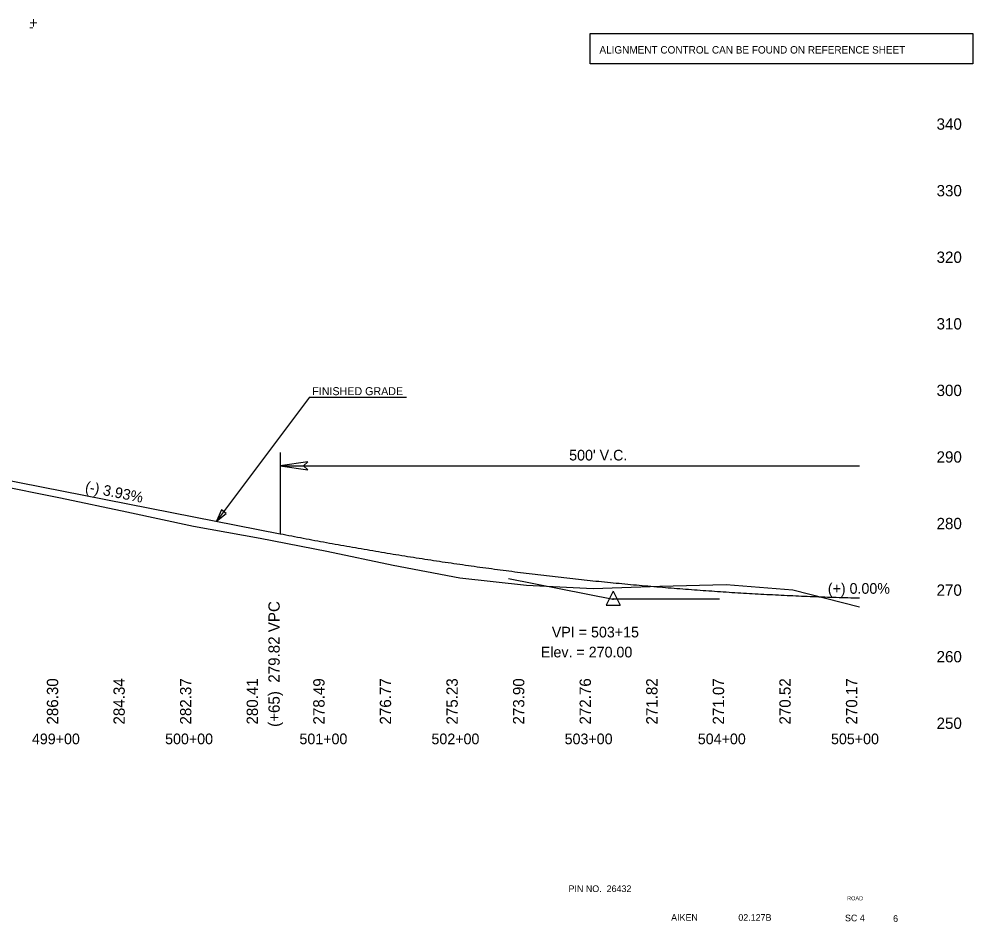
# Model space of a CAD drawing. Extents: x 48556 to 51363, y 45290 to 53458.
# Drawn here: x 50057 to 50773, y 46530 to 47208 of the extents above; entities that cross this region are included whole.
import ezdxf

# ---------------------------------------------------------------- set-up
doc = ezdxf.new("R2010")
doc.units = 0
for name, color, linetype in [('Level 1', 7, 'Continuous'), ('Level 24', 7, 'Continuous'), ('Level 25', 7, 'Continuous'), ('Level 40', 7, 'Continuous'), ('Level 41', 7, 'Continuous'), ('Level 42', 7, 'Continuous'), ('Level 43', 7, 'Continuous'), ('Level 45', 7, 'Continuous')]:
    doc.layers.add(name, color=color, linetype=linetype)

msp = doc.modelspace()

# ---------------------------------------------------------------- linework, layer by layer
at = {"layer": 'Level 1'}
for p, q in [((50275, 46924.38), (50205.18, 46831.33)), ((50275, 46924.38), (50347.79, 46924.38)), ((50502.91, 46778.85), (50497.66, 46768.35)), ((50502.91, 46778.85), (50508.16, 46768.35)), ((50497.66, 46768.35), (50508.16, 46768.35))]:
    msp.add_line(p, q, dxfattribs=at)
msp.add_lwpolyline([(50252.91, 46872.85), (50273.68, 46869.85), (50270.48, 46872.85), (50273.68, 46875.85)], close=True, dxfattribs=at)
msp.add_circle((50502.91, 46772.85), 0.375, dxfattribs=at)
at = {"layer": 'Level 24'}
for p, q in [((50208.79, 46839.88), (50205.18, 46831.33)), ((50212.39, 46837.17), (50208.79, 46839.88)), ((50205.18, 46831.33), (50212.39, 46837.17))]:
    msp.add_line(p, q, dxfattribs=at)
at = {"layer": 'Level 25'}
msp.add_lwpolyline([(50485.79, 47197.68), (50773.11, 47197.68), (50773.11, 47174.97), (50485.79, 47174.97)], close=True, dxfattribs=at)
at = {"layer": 'Level 40'}
msp.add_lwpolyline([(50037.91, 46858.99), (50087.91, 46848.83), (50137.91, 46838.48), (50187.91, 46827.57), (50237.91, 46818.6), (50287.91, 46808.73), (50337.91, 46798.21), (50387.91, 46788.76), (50437.91, 46783.23), (50487.91, 46780.68), (50537.91, 46782.44), (50587.91, 46783.93), (50637.91, 46779.7), (50687.91, 46767.11)], dxfattribs=at)
at = {"layer": 'Level 41'}
for p, q in [((50252.91, 46882.85), (50252.91, 46821.95)), ((50252.91, 46872.85), (50687.91, 46872.85)), ((50424.41, 46788.27), (50502.91, 46772.85)), ((50582.91, 46772.85), (50502.91, 46772.85))]:
    msp.add_line(p, q, dxfattribs=at)
at = {"layer": 'Level 45'}
msp.add_line((50037.91, 46864.18), (50252.91, 46821.95), dxfattribs=at)
msp.add_spline([(50252.91, 46821.95), (50261.61, 46820.26), (50270.31, 46818.59), (50279.01, 46816.96), (50287.71, 46815.36), (50296.41, 46813.78), (50305.11, 46812.24), (50313.81, 46810.72), (50322.51, 46809.23), (50331.21, 46807.78), (50339.91, 46806.35), (50348.61, 46804.96), (50357.31, 46803.59), (50366.01, 46802.25), (50374.71, 46800.94), (50383.41, 46799.67), (50392.11, 46798.42), (50400.81, 46797.2), (50409.51, 46796.01), (50418.21, 46794.85), (50426.91, 46793.72), (50435.61, 46792.63), (50444.31, 46791.56), (50453.01, 46790.52), (50461.71, 46789.51), (50470.41, 46788.53), (50479.11, 46787.58), (50487.81, 46786.65), (50496.51, 46785.76), (50505.21, 46784.9), (50513.91, 46784.07), (50522.61, 46783.27), (50531.31, 46782.5), (50540.01, 46781.75), (50548.71, 46781.04), (50557.41, 46780.36), (50566.11, 46779.7), (50574.81, 46779.08), (50583.51, 46778.49), (50592.21, 46777.92), (50600.91, 46777.39), (50609.61, 46776.88), (50618.31, 46776.41), (50627.01, 46775.96), (50635.71, 46775.55), (50644.41, 46775.16), (50653.11, 46774.81), (50661.81, 46774.48), (50670.51, 46774.18), (50679.21, 46773.92), (50687.91, 46773.68)], degree=3, dxfattribs=at)

# ---------------------------------------------------------------- texts
at = {"layer": 'Level 1'}
for s, height, p in [('+', 8, (50064.55, 47201.76)), ('-', 8, (50064.39, 47198.83)), ('FINISHED GRADE', 6, (50277.07, 46926.01))]:
    msp.add_text(s, height=height, dxfattribs=at).set_placement(p)
at = {"layer": 'Level 24'}
for s, height, p in [('PIN NO.  26432', 5, (50469.47, 46552.81)), ('ROAD', 3, (50678.66, 46546.63)), ('AIKEN', 5, (50546.51, 46531.23)), ('02.127B', 5, (50596.96, 46531.23)), ('SC 4', 5, (50677.06, 46530.84)), ('6', 5, (50713.17, 46530.45))]:
    msp.add_text(s, height=height, dxfattribs=at).set_placement(p)
at = {"layer": 'Level 25'}
msp.add_text('ALIGNMENT CONTROL CAN BE FOUND ON REFERENCE SHEET', height=5.6, dxfattribs=at).set_placement((50492.68, 47182.57))
at = {"layer": 'Level 41'}
for s, p in [("500' V.C.", (50469.96, 46876.95)), ('(+) 0.00%', (50664.15, 46776.85)), ('VPI = 503+15', (50456.92, 46744.06)), ('Elev. = 270.00', (50448.67, 46729.06))]:
    msp.add_text(s, height=8, dxfattribs=at).set_placement(p)
for s, height, rotation, p in [('(-) 3.93%', 8, 348.88825, (50106.02, 46853.64)), ('(+65)  279.82 VPC', 8.5, 90, (50252.61, 46676.87))]:
    msp.add_text(s, height=height, rotation=rotation, dxfattribs=at).set_placement(p)
at = {"layer": 'Level 42'}
for s, height, p in [('340', 8.5, (50745.83, 47125.35)), ('330', 8.5, (50745.83, 47075.35)), ('320', 8.5, (50745.83, 47025.35)), ('310', 8.5, (50745.83, 46975.35)), ('300', 8.5, (50745.83, 46925.35)), ('290', 8.5, (50745.83, 46875.35)), ('280', 8.5, (50745.83, 46825.35)), ('270', 8.5, (50745.83, 46775.35)), ('260', 8.5, (50745.83, 46725.35)), ('250', 8.5, (50745.83, 46675.35)), ('499+00', 8, (50066.55, 46663.85)), ('500+00', 8, (50166.55, 46663.85)), ('501+00', 8, (50267.42, 46663.85)), ('502+00', 8, (50366.55, 46663.85)), ('503+00', 8, (50466.55, 46663.85)), ('504+00', 8, (50566.55, 46663.85)), ('505+00', 8, (50666.55, 46663.85))]:
    msp.add_text(s, height=height, dxfattribs=at).set_placement(p)
at = {"layer": 'Level 43'}
for s, p in [('286.30', (50086.28, 46678.61)), ('284.34', (50136.28, 46678.61)), ('282.37', (50186.28, 46678.61)), ('280.41', (50236.28, 46678.61)), ('278.49', (50286.28, 46678.61)), ('276.77', (50336.28, 46678.61)), ('275.23', (50386.28, 46678.61)), ('273.90', (50436.28, 46678.61)), ('272.76', (50486.28, 46678.61)), ('271.82', (50536.28, 46678.61)), ('271.07', (50586.28, 46678.61)), ('270.52', (50636.28, 46678.61)), ('270.17', (50686.28, 46678.61))]:
    msp.add_text(s, height=8.5, rotation=90, dxfattribs=at).set_placement(p)

doc.saveas('drawing.dxf')
